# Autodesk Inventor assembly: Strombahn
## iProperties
Title: Strombahn
Comments: HSLT
Company: Mayer & Müller AG Schaltgeräte
Created: 2005-12
Part Number: 340853 Strombahn
Document SubType Name: Assembly
Designer: I.Baliuc
Manufacturer: Standard
Standards Organization: Custom
Description: Strombahn
Zweck: Vorkontakt HSLT
Author: T.Messerschmitt
Revision Number: 340853
